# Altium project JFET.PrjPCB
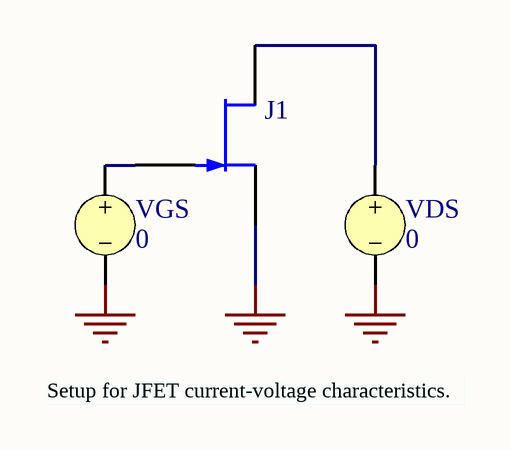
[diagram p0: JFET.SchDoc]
1 sheet, 3 parts. Net scope: global (net labels, ports and power ports of the same name join across sheets).

## Sheet JFET.SchDoc: JFET
size A; DocumentNumber: 1; SheetNumber: 1; SheetTotal: 1

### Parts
J1  NE38018-T1  [SOT343/P1.3]  (value not drawn)
VDS  value 0  (hidden comment: VSRC)
VGS  value 0  (hidden comment: VSRC)

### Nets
GND: J1.1(S) VDS.2 VGS.2
NetJ1_2: J1.2(G) VGS.1
NetJ1_4: J1.4(D) VDS.1

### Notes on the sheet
- Setup for JFET current-voltage characteristics.

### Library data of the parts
J1 = NE38018-T1: N-channel junction fet
VDS VGS = VSRC: Voltage Source; Manufacturer: Generic Components; Class: Simulation; Note: PCB Footprint - Not required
